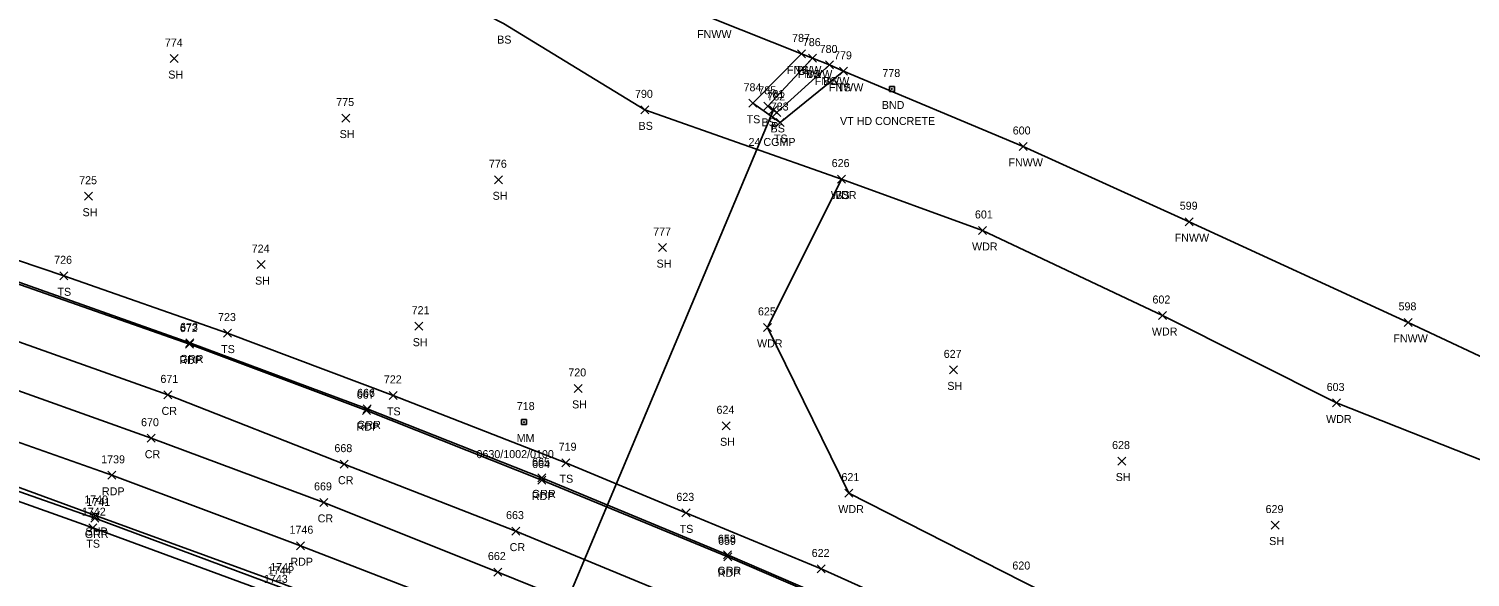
# Model space of a CAD drawing. Extents: x 1629176 to 1637209, y 606063 to 610167.
# Drawn here: x 1630075.4 to 1630435.7, y 606860.2 to 606997.3 of the extents above; entities that cross this region are included whole.
import ezdxf

# ---------------------------------------------------------------- set-up
doc = ezdxf.new("R2010")
doc.units = 0
for name, color, linetype in [('D_A', 7, 'Continuous'), ('D_C', 7, 'Continuous'), ('D_I', 7, 'Continuous'), ('D_TIC', 7, 'Continuous'), ('DCP', 7, 'Continuous'), ('L_A', 7, 'Continuous'), ('L_I', 7, 'Continuous'), ('L_TIC', 7, 'Continuous'), ('LAWA', 7, 'Continuous'), ('LELB', 7, 'Continuous'), ('LFNC', 7, 'Continuous'), ('M_A', 7, 'Continuous'), ('M_C', 7, 'Continuous'), ('M_I', 7, 'Continuous'), ('MHBP', 7, 'Continuous'), ('P_A', 7, 'Continuous'), ('P_I', 7, 'Continuous'), ('P_TIC', 7, 'Continuous'), ('PET', 7, 'Continuous'), ('PRC', 7, 'Continuous'), ('PSP', 7, 'Continuous'), ('R_A', 7, 'Continuous'), ('R_I', 7, 'Continuous'), ('R_TIC', 7, 'Continuous'), ('RGR', 7, 'Continuous'), ('S_A', 7, 'Continuous'), ('S_C', 7, 'Continuous'), ('S_I', 7, 'Continuous'), ('SRM', 7, 'Continuous')]:
    doc.layers.add(name, color=color, linetype=linetype)

msp = doc.modelspace()

# ---------------------------------------------------------------- linework, layer by layer
at = {"layer": 'D_TIC'}
for points in [[(1630260.59, 606975.98), (1630262.59, 606977.98)], [(1630262.59, 606975.98), (1630260.59, 606977.98)]]:
    msp.add_lwpolyline(points, dxfattribs=at)
at = {"layer": 'DCP'}
msp.add_lwpolyline([(1630261.59, 606976.98), (1630164.99, 606747.26)], dxfattribs=at)
at = {"layer": 'L_TIC'}
for points in [[(1630267.56, 606989.98), (1630269.56, 606991.98)], [(1630269.56, 606989.98), (1630267.56, 606991.98)], [(1630267.56, 606989.98), (1630269.56, 606991.98)], [(1630269.56, 606989.98), (1630267.56, 606991.98)], [(1630110.81, 606988.82), (1630112.81, 606990.82)], [(1630112.81, 606988.82), (1630110.81, 606990.82)], [(1630270.3, 606988.93), (1630272.3, 606990.93)], [(1630272.3, 606988.93), (1630270.3, 606990.93)], [(1630270.3, 606988.93), (1630272.3, 606990.93)], [(1630272.3, 606988.93), (1630270.3, 606990.93)], [(1630274.54, 606987.22), (1630276.54, 606989.22)], [(1630276.54, 606987.22), (1630274.54, 606989.22)], [(1630274.54, 606987.22), (1630276.54, 606989.22)], [(1630276.54, 606987.22), (1630274.54, 606989.22)], [(1630278.06, 606985.64), (1630280.06, 606987.64)], [(1630280.06, 606985.64), (1630278.06, 606987.64)], [(1630278.06, 606985.64), (1630280.06, 606987.64)], [(1630280.06, 606985.64), (1630278.06, 606987.64)], [(1630228.39, 606976), (1630230.39, 606978)], [(1630230.39, 606976), (1630228.39, 606978)], [(1630255.43, 606977.65), (1630257.43, 606979.65)], [(1630257.43, 606977.65), (1630255.43, 606979.65)], [(1630259.12, 606976.89), (1630261.12, 606978.89)], [(1630261.12, 606976.89), (1630259.12, 606978.89)], [(1630153.65, 606973.95), (1630155.65, 606975.95)], [(1630155.65, 606973.95), (1630153.65, 606975.95)], [(1630261.39, 606975.36), (1630263.39, 606977.36)], [(1630263.39, 606975.36), (1630261.39, 606977.36)], [(1630262.25, 606972.83), (1630264.25, 606974.83)], [(1630264.25, 606972.83), (1630262.25, 606974.83)], [(1630322.93, 606966.85), (1630324.93, 606968.85)], [(1630324.93, 606966.85), (1630322.93, 606968.85)], [(1630191.86, 606958.53), (1630193.86, 606960.53)], [(1630193.86, 606958.53), (1630191.86, 606960.53)], [(1630277.57, 606958.7), (1630279.57, 606960.7)], [(1630279.57, 606958.7), (1630277.57, 606960.7)], [(1630277.57, 606958.7), (1630279.57, 606960.7)], [(1630279.57, 606958.7), (1630277.57, 606960.7)], [(1630089.39, 606954.42), (1630091.39, 606956.42)], [(1630091.39, 606954.42), (1630089.39, 606956.42)], [(1630364.46, 606948.05), (1630366.46, 606950.05)], [(1630366.46, 606948.05), (1630364.46, 606950.05)], [(1630312.82, 606945.86), (1630314.82, 606947.86)], [(1630314.82, 606945.86), (1630312.82, 606947.86)], [(1630232.84, 606941.58), (1630234.84, 606943.58)], [(1630234.84, 606941.58), (1630232.84, 606943.58)], [(1630132.5, 606937.33), (1630134.5, 606939.33)], [(1630134.5, 606937.33), (1630132.5, 606939.33)], [(1630083.2, 606934.53), (1630085.2, 606936.53)], [(1630085.2, 606934.53), (1630083.2, 606936.53)], [(1630171.92, 606921.94), (1630173.92, 606923.94)], [(1630173.92, 606921.94), (1630171.92, 606923.94)], [(1630259.08, 606921.64), (1630261.08, 606923.64)], [(1630261.08, 606921.64), (1630259.08, 606923.64)], [(1630357.76, 606924.61), (1630359.76, 606926.61)], [(1630359.76, 606924.61), (1630357.76, 606926.61)], [(1630419.14, 606922.9), (1630421.14, 606924.9)], [(1630421.14, 606922.9), (1630419.14, 606924.9)], [(1630124.1, 606920.22), (1630126.1, 606922.22)], [(1630126.1, 606920.22), (1630124.1, 606922.22)], [(1630305.51, 606911.02), (1630307.51, 606913.02)], [(1630307.51, 606911.02), (1630305.51, 606913.02)], [(1630165.54, 606904.65), (1630167.54, 606906.65)], [(1630167.54, 606904.65), (1630165.54, 606906.65)], [(1630211.73, 606906.39), (1630213.73, 606908.39)], [(1630213.73, 606906.39), (1630211.73, 606908.39)], [(1630401.3, 606902.75), (1630403.3, 606904.75)], [(1630403.3, 606902.75), (1630401.3, 606904.75)], [(1630248.71, 606897.05), (1630250.71, 606899.05)], [(1630250.71, 606897.05), (1630248.71, 606899.05)], [(1630208.67, 606887.82), (1630210.67, 606889.82)], [(1630210.67, 606887.82), (1630208.67, 606889.82)], [(1630347.59, 606888.24), (1630349.59, 606890.24)], [(1630349.59, 606888.24), (1630347.59, 606890.24)], [(1630279.39, 606880.23), (1630281.39, 606882.23)], [(1630281.39, 606880.23), (1630279.39, 606882.23)], [(1630238.69, 606875.29), (1630240.69, 606877.29)], [(1630240.69, 606875.29), (1630238.69, 606877.29)], [(1630090.41, 606871.59), (1630092.41, 606873.59)], [(1630092.41, 606871.59), (1630090.41, 606873.59)], [(1630385.96, 606872.24), (1630387.96, 606874.24)], [(1630387.96, 606872.24), (1630385.96, 606874.24)], [(1630272.51, 606861.27), (1630274.51, 606863.27)], [(1630274.51, 606861.27), (1630272.51, 606863.27)]]:
    msp.add_lwpolyline(points, dxfattribs=at)
at = {"layer": 'LAWA'}
for points in [[(1630313.82, 606946.86), (1630358.76, 606925.61), (1630402.3, 606903.75), (1630450.92, 606884.57), (1630493.61, 606863.97), (1630542.51, 606827.97), (1630547.78, 606801.97), (1630542.32, 606780.41), (1630525.99, 606758.91), (1630486.85, 606779.39), (1630438.5, 606804.18), (1630398.22, 606823.46), (1630362.92, 606839.59), (1630323.76, 606859.13), (1630280.39, 606881.23), (1630260.08, 606922.64), (1630278.57, 606959.7)], [(1630278.57, 606959.7), (1630313.82, 606946.86)]]:
    msp.add_lwpolyline(points, dxfattribs=at)
at = {"layer": 'LELB'}
for points in [[(1630278.57, 606959.7), (1630229.39, 606977), (1630194.06, 606998.56), (1630148.22, 607022.11), (1630112.85, 607030.14), (1630114.89, 607063.51)], [(1630279.06, 606986.64), (1630263.25, 606973.83), (1630256.43, 606978.65), (1630268.56, 606990.98)], [(1630275.54, 606988.22), (1630262.39, 606976.36), (1630260.12, 606977.89), (1630271.3, 606989.93)], [(1630772.3, 606583.26), (1630744.36, 606600.82), (1630702.09, 606628.01), (1630669.73, 606653.69), (1630639.16, 606677.6), (1630625.62, 606682.65), (1630575.5, 606708.79), (1630543.73, 606726.11), (1630517.88, 606742.14), (1630478.23, 606762.96), (1630430.43, 606788.65), (1630392.8, 606806.98), (1630357.66, 606823.31), (1630317.9, 606842.29), (1630273.51, 606862.27), (1630239.69, 606876.29), (1630209.67, 606888.82), (1630166.54, 606905.65), (1630125.1, 606921.22), (1630084.2, 606935.53), (1630049.16, 606947.36)], [(1630044.25, 606889.35), (1630091.41, 606872.59), (1630136.9, 606855.8), (1630181.87, 606838.43), (1630229.1, 606819.13), (1630265.76, 606803.15), (1630304.81, 606785.31), (1630348.18, 606765.13), (1630385.69, 606747.11), (1630426.71, 606726.12), (1630450.89, 606713.6)]]:
    msp.add_lwpolyline(points, dxfattribs=at)
at = {"layer": 'LFNC'}
msp.add_lwpolyline([(1630711.29, 606778.57), (1630698.29, 606772.29), (1630652.28, 606800.26), (1630633.63, 606811.4), (1630600.09, 606830.6), (1630575.92, 606844.82), (1630561.53, 606852.75), (1630524.5, 606872.81), (1630472.01, 606899.53), (1630420.14, 606923.9), (1630365.46, 606949.05), (1630323.93, 606967.85), (1630279.06, 606986.64), (1630275.54, 606988.22), (1630271.3, 606989.93), (1630268.56, 606990.98), (1630246.11, 606999.94), (1630223.72, 607008.56), (1630189.18, 607022.51), (1630178, 607040.55), (1630154.89, 607078.39)], dxfattribs=at)
at = {"layer": 'MHBP'}
for p, q in [((1630291.79, 606982.88), (1630290.54, 606982.88)), ((1630290.54, 606982.88), (1630290.54, 606981.63)), ((1630291.79, 606982.88), (1630290.54, 606982.88)), ((1630290.54, 606982.88), (1630290.54, 606981.63)), ((1630290.54, 606981.63), (1630291.79, 606981.63)), ((1630290.54, 606981.63), (1630291.79, 606981.63)), ((1630291.79, 606981.63), (1630291.79, 606982.88)), ((1630291.79, 606981.63), (1630291.79, 606982.88))]:
    msp.add_line(p, q, dxfattribs=at)
msp.add_circle((1630291.14, 606982.22), 0.0833, dxfattribs=at)
at = {"layer": 'P_TIC'}
for points in [[(1630114.59, 606917.47), (1630116.59, 606919.47)], [(1630116.59, 606917.47), (1630114.59, 606919.47)], [(1630109.18, 606904.77), (1630111.18, 606906.77)], [(1630111.18, 606904.77), (1630109.18, 606906.77)], [(1630158.86, 606900.83), (1630160.86, 606902.83)], [(1630160.86, 606900.83), (1630158.86, 606902.83)], [(1630104.99, 606893.95), (1630106.99, 606895.95)], [(1630106.99, 606893.95), (1630104.99, 606895.95)], [(1630153.28, 606887.46), (1630155.28, 606889.46)], [(1630155.28, 606887.46), (1630153.28, 606889.46)], [(1630095.23, 606884.67), (1630097.23, 606886.67)], [(1630097.23, 606884.67), (1630095.23, 606886.67)], [(1630202.69, 606883.49), (1630204.69, 606885.49)], [(1630204.69, 606883.49), (1630202.69, 606885.49)], [(1630091.08, 606874.64), (1630093.08, 606876.64)], [(1630093.08, 606874.64), (1630091.08, 606876.64)], [(1630148.2, 606877.91), (1630150.2, 606879.91)], [(1630150.2, 606877.91), (1630148.2, 606879.91)], [(1630196.18, 606870.73), (1630198.18, 606872.73)], [(1630198.18, 606870.73), (1630196.18, 606872.73)], [(1630142.35, 606867.08), (1630144.35, 606869.08)], [(1630144.35, 606867.08), (1630142.35, 606869.08)], [(1630249.13, 606864.31), (1630251.13, 606866.31)], [(1630251.13, 606864.31), (1630249.13, 606866.31)], [(1630191.63, 606860.5), (1630193.63, 606862.5)], [(1630193.63, 606860.5), (1630191.63, 606862.5)]]:
    msp.add_lwpolyline(points, dxfattribs=at)
at = {"layer": 'PET'}
for points in [[(1630769.62, 606580.83), (1630742.32, 606598.72), (1630700.55, 606625.63), (1630665.45, 606648.34), (1630621.98, 606674.98), (1630606.18, 606684.39), (1630572.37, 606704.1), (1630541.12, 606722.17), (1630498.96, 606745.43), (1630457.51, 606767.81), (1630420.78, 606786.67), (1630374.62, 606809.25), (1630335.12, 606827.65), (1630289.38, 606848.42), (1630250.13, 606865.31), (1630203.69, 606884.49), (1630159.86, 606901.83), (1630115.59, 606918.47), (1630070.26, 606934.37)], [(1630050.76, 606901.68), (1630096.23, 606885.67), (1630143.35, 606868.08), (1630186.15, 606851.44), (1630235.05, 606831.31), (1630271.1, 606815.81), (1630310.69, 606798.07), (1630353.79, 606777.93), (1630392.73, 606758.86), (1630432.29, 606738.62), (1630464.02, 606722.09), (1630502.44, 606701.07), (1630537.98, 606680.83), (1630570.03, 606662.27), (1630609.11, 606638.58), (1630644.7, 606616.38), (1630681.38, 606592.72), (1630715.14, 606570.86), (1630750.81, 606547.81)]]:
    msp.add_lwpolyline(points, dxfattribs=at)
at = {"layer": 'PRC'}
for points in [[(1630762, 606568.31), (1630732.48, 606587.66), (1630693.14, 606613.4), (1630657.5, 606636.16), (1630615.44, 606661.97), (1630565.18, 606692.12), (1630533.4, 606710.56), (1630491.42, 606733.47), (1630450.45, 606755.19), (1630412.78, 606774.87), (1630369.5, 606796.13), (1630328.6, 606815.23), (1630283.03, 606835.75), (1630244.34, 606852.21), (1630197.18, 606871.73), (1630154.28, 606888.46), (1630110.18, 606905.77), (1630065.36, 606921.68)], [(1630755.45, 606559.52), (1630726, 606578.65), (1630686.27, 606604.3), (1630651.63, 606626.53), (1630610.5, 606651.79), (1630559.24, 606682.64), (1630527.45, 606700.94), (1630485.76, 606723.98), (1630445.96, 606745.41), (1630407.11, 606765.59), (1630364.16, 606786.66), (1630323.37, 606805.55), (1630278.9, 606825.47), (1630240.3, 606842.26), (1630192.63, 606861.5), (1630149.2, 606878.91), (1630105.99, 606894.95), (1630061.18, 606910.94)]]:
    msp.add_lwpolyline(points, dxfattribs=at)
at = {"layer": 'PSP'}
msp.add_lwpolyline([(1630045.28, 606892.75), (1630092.08, 606875.64), (1630138.49, 606858.75), (1630183.19, 606841.37), (1630230, 606822.13), (1630266.88, 606805.89), (1630306.04, 606788.47), (1630348.79, 606768.34), (1630387.17, 606749.74), (1630427.91, 606728.87), (1630457.64, 606713.36), (1630497.17, 606691.94), (1630531.87, 606672.45), (1630564.31, 606653.82), (1630602.72, 606629.92), (1630638.6, 606607.1), (1630675.39, 606583.77), (1630709.63, 606561.3), (1630744.78, 606538.28)], dxfattribs=at)
at = {"layer": 'R_TIC'}
for points in [[(1630114.67, 606917.76), (1630116.67, 606919.76)], [(1630116.67, 606917.76), (1630114.67, 606919.76)], [(1630159.01, 606901.28), (1630161.01, 606903.28)], [(1630161.01, 606901.28), (1630159.01, 606903.28)], [(1630202.7, 606884.03), (1630204.7, 606886.03)], [(1630204.7, 606884.03), (1630202.7, 606886.03)], [(1630090.95, 606874), (1630092.95, 606876)], [(1630092.95, 606874), (1630090.95, 606876)], [(1630249.07, 606864.82), (1630251.07, 606866.82)], [(1630251.07, 606864.82), (1630249.07, 606866.82)]]:
    msp.add_lwpolyline(points, dxfattribs=at)
at = {"layer": 'RGR'}
for points in [[(1630636.53, 606670.83), (1630623.24, 606676.36), (1630606.52, 606684.67), (1630573.19, 606704.3), (1630541.55, 606722.4), (1630499.19, 606745.82), (1630457.55, 606768.16), (1630421.01, 606787.01), (1630374.76, 606809.6), (1630335.39, 606828.12), (1630289.48, 606848.85), (1630250.07, 606865.82), (1630203.7, 606885.03), (1630160.01, 606902.28), (1630115.67, 606918.76), (1630070.66, 606934.74)], [(1630044.87, 606891.43), (1630091.95, 606875), (1630137.84, 606857.9), (1630182.67, 606840.57), (1630230.01, 606820.88), (1630266.36, 606805.24), (1630305.77, 606787.45), (1630348.91, 606767.39), (1630386.68, 606748.91), (1630427.72, 606728.18), (1630457.43, 606712.48), (1630496.65, 606691.24), (1630531.18, 606671.77), (1630563.73, 606652.86), (1630574.41, 606646.66), (1630584.49, 606638.94), (1630594.27, 606630.4)]]:
    msp.add_lwpolyline(points, dxfattribs=at)
at = {"layer": 'SRM'}
for p, q in [((1630199.84, 606899.63), (1630198.59, 606899.63)), ((1630198.59, 606899.63), (1630198.59, 606898.38)), ((1630199.84, 606899.63), (1630198.59, 606899.63)), ((1630198.59, 606899.63), (1630198.59, 606898.38)), ((1630198.59, 606898.38), (1630199.84, 606898.38)), ((1630198.59, 606898.38), (1630199.84, 606898.38)), ((1630199.84, 606898.38), (1630199.84, 606899.63)), ((1630199.84, 606898.38), (1630199.84, 606899.63))]:
    msp.add_line(p, q, dxfattribs=at)
msp.add_circle((1630199.19, 606898.96), 0.0833, dxfattribs=at)

# ---------------------------------------------------------------- texts
at = {"layer": 'D_A'}
msp.add_text('P', height=2, dxfattribs=at).set_placement((1630260.97, 606971.98))
at = {"layer": 'D_C'}
msp.add_text('24 CGMP', height=2, dxfattribs=at).set_placement((1630255.32, 606967.98))
at = {"layer": 'D_I'}
msp.add_text('781', height=2, dxfattribs=at).set_placement((1630259.8, 606979.98))
at = {"layer": 'L_A'}
for s, p in [('BS', (1630192.5, 606993.56)), ('FNWW', (1630242.46, 606994.94)), ('SH', (1630110.3, 606984.82)), ('FNWW', (1630264.91, 606985.98)), ('TS', (1630266.97, 606985.98)), ('FNWW', (1630267.64, 606984.93)), ('BS', (1630269.74, 606984.93)), ('FNWW', (1630271.89, 606983.22)), ('BS', (1630273.98, 606983.22)), ('FNWW', (1630275.41, 606981.64)), ('TS', (1630277.47, 606981.64)), ('BS', (1630227.83, 606972)), ('TS', (1630254.84, 606973.65)), ('BS', (1630258.56, 606972.89)), ('SH', (1630153.13, 606969.95)), ('BS', (1630260.83, 606971.36)), ('TS', (1630261.66, 606968.83)), ('FNWW', (1630320.27, 606962.85)), ('SH', (1630191.35, 606954.53)), ('WDR', (1630275.93, 606954.7)), ('BS', (1630277.01, 606954.7)), ('SH', (1630088.88, 606950.42)), ('FNWW', (1630361.81, 606944.05)), ('WDR', (1630311.18, 606941.86)), ('SH', (1630232.33, 606937.58)), ('SH', (1630131.99, 606933.33)), ('TS', (1630082.6, 606930.53)), ('SH', (1630171.4, 606917.94)), ('WDR', (1630356.12, 606920.61)), ('FNWW', (1630416.48, 606918.9)), ('TS', (1630123.51, 606916.22)), ('WDR', (1630257.44, 606917.64)), ('SH', (1630305, 606907.02)), ('TS', (1630164.95, 606900.65)), ('SH', (1630211.22, 606902.39)), ('WDR', (1630399.66, 606898.75)), ('SH', (1630248.2, 606893.05)), ('TS', (1630208.08, 606883.82)), ('SH', (1630347.08, 606884.24)), ('WDR', (1630277.75, 606876.23)), ('TS', (1630238.1, 606871.29)), ('TS', (1630089.82, 606867.59)), ('SH', (1630385.44, 606868.24))]:
    msp.add_text(s, height=2, dxfattribs=at).set_placement(p)
at = {"layer": 'L_I'}
for s, p in [('787', (1630266.2, 606993.98)), ('787', (1630266.2, 606993.98)), ('774', (1630109.45, 606992.82)), ('786', (1630268.88, 606992.93)), ('786', (1630268.88, 606992.93)), ('780', (1630273.09, 606991.22)), ('780', (1630273.09, 606991.22)), ('779', (1630276.69, 606989.64)), ('779', (1630276.69, 606989.64)), ('790', (1630226.94, 606980)), ('784', (1630254.07, 606981.65)), ('785', (1630257.75, 606980.89)), ('782', (1630260.02, 606979.36)), ('775', (1630152.28, 606977.95)), ('783', (1630260.88, 606976.83)), ('600', (1630321.35, 606970.85)), ('776', (1630190.44, 606962.53)), ('626', (1630276.1, 606962.7)), ('626', (1630276.1, 606962.7)), ('725', (1630088.03, 606958.42)), ('599', (1630363.09, 606952.05)), ('601', (1630311.9, 606949.86)), ('777', (1630231.48, 606945.58)), ('724', (1630131.14, 606941.33)), ('726', (1630081.78, 606938.53)), ('721', (1630171.12, 606925.94)), ('625', (1630257.67, 606925.64)), ('602', (1630356.27, 606928.61)), ('598', (1630417.77, 606926.9)), ('723', (1630122.74, 606924.22)), ('627', (1630304.1, 606915.02)), ('722', (1630164.18, 606908.65)), ('720', (1630210.28, 606910.39)), ('603', (1630399.81, 606906.75)), ('624', (1630247.31, 606901.05)), ('719', (1630207.87, 606891.82)), ('628', (1630346.18, 606892.24)), ('621', (1630278.54, 606884.23)), ('623', (1630237.28, 606879.29)), ('1742', (1630088.72, 606875.59)), ('629', (1630384.54, 606876.24)), ('622', (1630271.1, 606865.27)), ('620', (1630321.26, 606862.13)), ('1743', (1630134.2, 606858.8))]:
    msp.add_text(s, height=2, dxfattribs=at).set_placement(p)
at = {"layer": 'M_A'}
msp.add_text('BND', height=2, dxfattribs=at).set_placement((1630288.62, 606977.22))
at = {"layer": 'M_C'}
msp.add_text('VT HD CONCRETE', height=2, dxfattribs=at).set_placement((1630278.18, 606973.22))
at = {"layer": 'M_I'}
msp.add_text('778', height=2, dxfattribs=at).set_placement((1630288.77, 606985.22))
at = {"layer": 'P_A'}
for s, p in [('RDP', (1630113.08, 606913.47)), ('CR', (1630108.62, 606900.77)), ('RDP', (1630157.35, 606896.83)), ('CR', (1630104.43, 606889.95)), ('CR', (1630152.71, 606883.46)), ('RDP', (1630093.72, 606880.67)), ('RDP', (1630201.17, 606879.49)), ('CR', (1630147.63, 606873.91)), ('SHP', (1630089.62, 606870.64)), ('CR', (1630195.61, 606866.73)), ('RDP', (1630140.83, 606863.08)), ('RDP', (1630247.61, 606860.31))]:
    msp.add_text(s, height=2, dxfattribs=at).set_placement(p)
at = {"layer": 'P_I'}
for s, p in [('672', (1630113.18, 606921.47)), ('671', (1630108.34, 606908.77)), ('667', (1630157.4, 606904.83)), ('670', (1630103.5, 606897.95)), ('668', (1630151.82, 606891.46)), ('1739', (1630093.53, 606888.67)), ('664', (1630201.23, 606887.49)), ('669', (1630146.73, 606881.91)), ('1740', (1630089.3, 606878.64)), ('663', (1630194.72, 606874.73)), ('1746', (1630140.6, 606871.08)), ('659', (1630247.71, 606868.31)), ('662', (1630190.18, 606864.5)), ('1745', (1630135.79, 606861.75))]:
    msp.add_text(s, height=2, dxfattribs=at).set_placement(p)
at = {"layer": 'R_A'}
for p in [(1630113.15, 606913.76), (1630157.49, 606897.28), (1630201.19, 606880.03), (1630089.44, 606870), (1630247.55, 606860.82)]:
    msp.add_text('GRR', height=2, dxfattribs=at).set_placement(p)
at = {"layer": 'R_I'}
for s, p in [('673', (1630113.26, 606921.76)), ('666', (1630157.49, 606905.28)), ('665', (1630201.24, 606888.03)), ('1741', (1630089.83, 606878)), ('658', (1630247.66, 606868.82)), ('1744', (1630135.15, 606860.9))]:
    msp.add_text(s, height=2, dxfattribs=at).set_placement(p)
at = {"layer": 'S_A'}
msp.add_text('MM', height=2, dxfattribs=at).set_placement((1630197.38, 606893.97))
at = {"layer": 'S_C'}
msp.add_text('0630/1002/0100', height=2, dxfattribs=at).set_placement((1630187.33, 606889.97))
at = {"layer": 'S_I'}
msp.add_text('718', height=2, dxfattribs=at).set_placement((1630197.4, 606901.97))

doc.saveas('drawing.dxf')
